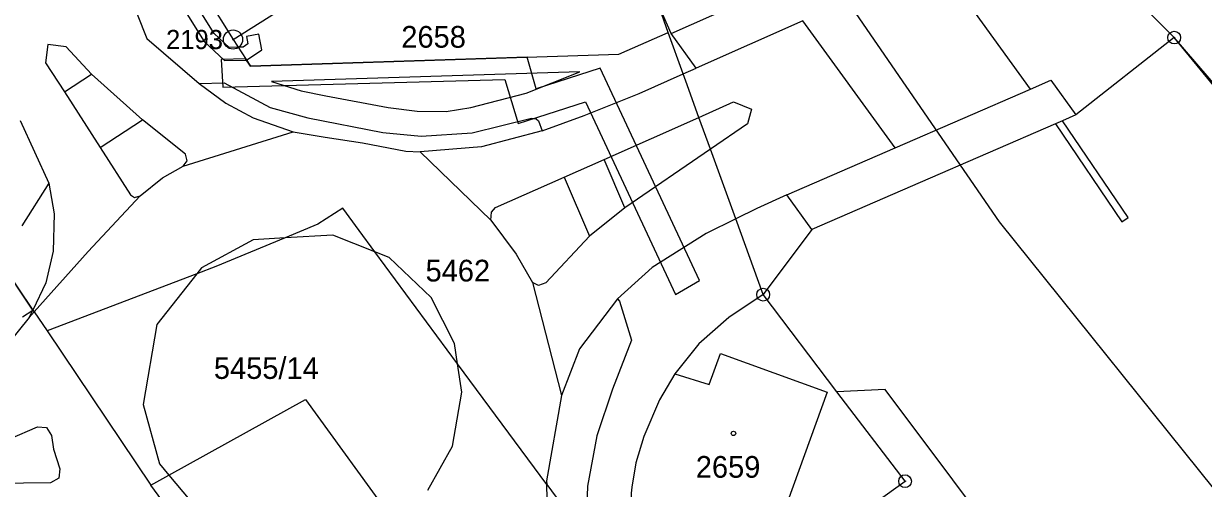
# Model space of a CAD drawing. Extents: x -821458 to -820266, y -1071458 to -1069826.
# Drawn here: x -820637.8 to -820545.4, y -1071330.5 to -1071294.1 of the extents above; entities that cross this region are included whole.
import ezdxf

# ---------------------------------------------------------------- set-up
doc = ezdxf.new("R2010")
doc.units = 0
for name, color, linetype in [('Vrstva 1', 7, 'Continuous'), ('Vrstva 13', 7, 'Continuous'), ('Vrstva 2', 7, 'Continuous'), ('Vrstva 4', 7, 'Continuous'), ('Vrstva 5', 7, 'Continuous'), ('Vrstva 6', 7, 'Continuous'), ('Vrstva 8', 7, 'Continuous')]:
    doc.layers.add(name, color=color, linetype=linetype)

msp = doc.modelspace()

# ---------------------------------------------------------------- linework, layer by layer
at = {"layer": 'Vrstva 1'}
for p, q in [((-820628.38, -1071284.03), (-820621.4, -1071295.3)), ((-820574.1, -1071322.9), (-820579.87, -1071315.28)), ((-820636.97, -1071316.64), (-820635.97, -1071318.12)), ((-820635.97, -1071318.12), (-820627.84, -1071330.19))]:
    msp.add_line(p, q, dxfattribs=at)
for points in [[(-820621.4, -1071295.3), (-820609.81, -1071287.99), (-820602.74, -1071283.57), (-820601.4, -1071282.71), (-820597.17, -1071279.98)], [(-820587.31, -1071294.74), (-820588.13, -1071292.45), (-820588.5, -1071292.71), (-820597.17, -1071279.98)], [(-820485.86, -1071372.383), (-820533.17, -1071312.78), (-820547.67, -1071295.15), (-820551.62, -1071291.15), (-820556.95, -1071290.24), (-820564.58, -1071281.57)], [(-820651.78, -1071294.5), (-820644.75, -1071305.17), (-820642.81, -1071308.03), (-820641.98, -1071309.26), (-820639.44, -1071313.01), (-820637.08, -1071316.49), (-820636.97, -1071316.64)], [(-820621.4, -1071295.3), (-820620.04, -1071297.4), (-820591.18, -1071296.46), (-820587.31, -1071294.74)], [(-820579.87, -1071315.28), (-820582.02, -1071309.35), (-820584, -1071303.9), (-820584.91, -1071301.4), (-820585.94, -1071298.56), (-820586.14, -1071298), (-820587.31, -1071294.74)], [(-820636.97, -1071316.64), (-820632.74, -1071311.9), (-820628.67, -1071307.54), (-820626.92, -1071306.13), (-820625.31, -1071305.23), (-820616.7, -1071302.53), (-820614.19, -1071302.96), (-820611.26, -1071303.39), (-820607.86, -1071304.05), (-820606.74, -1071304.09), (-820601.21, -1071309.45), (-820599.23, -1071312.11), (-820597.95, -1071314.34), (-820595.67, -1071323.19), (-820596.84, -1071329.86), (-820596.83, -1071330.15)], [(-820596.83, -1071330.15), (-820603.81, -1071320.7), (-820610.28, -1071311.94), (-820611.51, -1071310.27), (-820612.8, -1071308.52), (-820614.75, -1071309.77), (-820617.32, -1071310.83), (-820622.76, -1071313.08), (-820624.23, -1071313.64), (-820635.97, -1071318.12)], [(-820579.87, -1071315.28), (-820582.56, -1071317.06), (-820584.9, -1071319.14), (-820586.78, -1071321.49), (-820588, -1071323.53), (-820589.23, -1071326.4), (-820589.84, -1071328.44), (-820590.16, -1071330.36), (-820590.22, -1071330.83), (-820590.24, -1071333.93), (-820589.7, -1071337.1), (-820588.71, -1071340.28), (-820587.2, -1071343.19)], [(-820636.97, -1071316.64), (-820637.36, -1071317.08), (-820639.2, -1071319.35), (-820642.33, -1071322.43), (-820644.69, -1071324.22), (-820646.94, -1071325.71), (-820650.04, -1071327.31), (-820653.86, -1071329.02), (-820657.08, -1071330.4), (-820661.97, -1071331.85), (-820670.38, -1071333.7), (-820675.08, -1071335.1), (-820699.14, -1071345.77), (-820707.87, -1071352.56), (-820710.18, -1071353.88), (-820714.99, -1071355.97), (-820717.71, -1071357.17), (-820719.42, -1071357.95), (-820734.359, -1071365.197)], [(-820554.5, -1071343.84), (-820570.3, -1071322.7), (-820574.1, -1071322.9)], [(-820571.04, -1071331.54), (-820568.75, -1071329.89), (-820574.1, -1071322.9)], [(-820627.84, -1071330.19), (-820626.42, -1071329.41), (-820615.71, -1071323.48), (-820608.76, -1071333.11), (-820604.43, -1071339.12)], [(-820646.49, -1071330.09), (-820643.71, -1071328.69), (-820641.09, -1071327.51), (-820636.73, -1071325.64), (-820636, -1071325.69), (-820635.62, -1071326.31), (-820635.46, -1071327.37), (-820634.97, -1071328.91), (-820635.04, -1071329.66), (-820635.7, -1071330.02), (-820637.82, -1071330.05), (-820640.55, -1071330.14), (-820643.18, -1071330.76), (-820644.87, -1071331.37), (-820649.56, -1071333.47), (-820650.2, -1071333.24), (-820650.08, -1071332.51), (-820648.32, -1071331.22), (-820646.49, -1071330.09)], [(-820629.87, -1071337.4), (-820624.4, -1071334.89), (-820627.84, -1071330.19)], [(-820596.83, -1071330.15), (-820593.66, -1071334.44), (-820587.2, -1071343.19)], [(-820588.84, -1071349.46), (-820591.79, -1071345.45), (-820593.17, -1071343.03), (-820595.21, -1071338.98), (-820596.72, -1071334.72), (-820596.83, -1071330.15)]]:
    msp.add_lwpolyline(points, dxfattribs=at)
at = {"layer": 'Vrstva 13'}
for points in [[(-820650.46, -1071253.28), (-820636.39, -1071275.54), (-820629.91, -1071285.45), (-820623.66, -1071295.46), (-820622.08, -1071296.95), (-820620.34, -1071296.92), (-820619.15, -1071296.11), (-820619.37, -1071294.88), (-820620.35, -1071295.06), (-820620.25, -1071295.65), (-820620.61, -1071295.9), (-820621, -1071295.91), (-820621.7, -1071295.93), (-820622.88, -1071294.82), (-820628.8, -1071285.34), (-820627.91, -1071284.78), (-820628.38, -1071284.03), (-820628.44, -1071283.93), (-820629.34, -1071284.49), (-820635.43, -1071275.04), (-820634.47, -1071274.43), (-820635, -1071273.59), (-820635.97, -1071274.2), (-820643.14, -1071263.21)], [(-820637.9, -1071317.01), (-820637.08, -1071316.49), (-820638.4, -1071314.54)]]:
    msp.add_lwpolyline(points, dxfattribs=at)
msp.add_lwpolyline([(-820622.33, -1071296.86), (-820622.21, -1071299.02), (-820600.11, -1071298.43), (-820599.06, -1071301.87), (-820593.79, -1071300.18), (-820586.74, -1071315.27), (-820584.86, -1071314.18), (-820592.63, -1071297.54), (-820597.64, -1071299.15), (-820598.35, -1071296.69), (-820620.04, -1071297.4), (-820620.42, -1071296.81)], close=True, dxfattribs=at)
at = {"layer": 'Vrstva 4'}
for p, q in [((-820558.94, -1071299.19), (-820566.17, -1071289.15)), ((-820587.08, -1071294.82), (-820578.74, -1071291.13)), ((-820587.08, -1071294.82), (-820588.13, -1071292.45)), ((-820628.9, -1071293.32), (-820628.16, -1071295.22)), ((-820576.77, -1071293.84), (-820585.13, -1071297.55)), ((-820569.54, -1071303.79), (-820576.77, -1071293.84)), ((-820628.16, -1071295.22), (-820624.05, -1071298.74)), ((-820585.13, -1071297.55), (-820587.08, -1071294.82)), ((-820547.67, -1071295.15), (-820555.37, -1071301.21)), ((-820486.8, -1071365.91), (-820547.67, -1071295.15)), ((-820635.9, -1071295.68), (-820636.09, -1071297.12)), ((-820634.47, -1071295.88), (-820635.9, -1071295.68)), ((-820632.48, -1071298.01), (-820634.47, -1071295.88)), ((-820636.09, -1071297.12), (-820634.61, -1071299.39)), ((-820634.61, -1071299.39), (-820632.48, -1071298.01)), ((-820628.5, -1071301.58), (-820632.48, -1071298.01)), ((-820594.22, -1071297.82), (-820618.38, -1071298.58)), ((-820598.44, -1071299.5), (-820594.22, -1071297.82)), ((-820589.59, -1071299.52), (-820586.14, -1071298)), ((-820586.14, -1071298), (-820585.13, -1071297.55)), ((-820624.05, -1071298.74), (-820622.1, -1071298.7)), ((-820624.05, -1071298.74), (-820621.97, -1071300.28)), ((-820622.1, -1071298.7), (-820618.49, -1071300.63)), ((-820618.38, -1071298.58), (-820616.07, -1071299.32)), ((-820558.94, -1071299.19), (-820557.34, -1071298.49)), ((-820557.34, -1071298.49), (-820555.37, -1071301.21)), ((-820634.61, -1071299.39), (-820631.81, -1071303.75)), ((-820616.07, -1071299.32), (-820614.12, -1071299.71)), ((-820614.12, -1071299.71), (-820609.25, -1071300.63)), ((-820602.77, -1071300.62), (-820598.44, -1071299.5)), ((-820593.89, -1071301.26), (-820589.59, -1071299.52)), ((-820569.54, -1071303.79), (-820558.94, -1071299.19)), ((-820621.97, -1071300.28), (-820619.83, -1071301.44)), ((-820618.49, -1071300.63), (-820615.55, -1071301.43)), ((-820609.25, -1071300.63), (-820606.98, -1071300.9)), ((-820604.71, -1071300.94), (-820602.77, -1071300.62)), ((-820584.91, -1071301.4), (-820582.19, -1071300.19)), ((-820582.19, -1071300.19), (-820580.79, -1071300.76)), ((-820580.79, -1071300.76), (-820581.09, -1071301.91)), ((-820638.08, -1071301.63), (-820635.84, -1071306.55)), ((-820631.81, -1071303.75), (-820628.5, -1071301.58)), ((-820625.13, -1071304.27), (-820628.5, -1071301.58)), ((-820619.83, -1071301.44), (-820616.7, -1071302.53)), ((-820615.55, -1071301.43), (-820609.66, -1071302.59)), ((-820606.98, -1071300.9), (-820604.71, -1071300.94)), ((-820602.67, -1071302.62), (-820598.01, -1071301.46)), ((-820598.01, -1071301.46), (-820597.66, -1071301.51)), ((-820597.66, -1071301.51), (-820597.46, -1071301.67)), ((-820597.46, -1071301.67), (-820597.18, -1071302.44)), ((-820597.18, -1071302.44), (-820593.89, -1071301.26)), ((-820592.33, -1071304.69), (-820584.91, -1071301.4)), ((-820556.42, -1071301.67), (-820556.98, -1071301.91)), ((-820555.37, -1071301.21), (-820556.42, -1071301.67)), ((-820551.27, -1071309.23), (-820556.42, -1071301.67)), ((-820609.66, -1071302.59), (-820606.66, -1071302.86)), ((-820606.66, -1071302.86), (-820602.67, -1071302.62)), ((-820597.18, -1071302.44), (-820601.93, -1071303.7)), ((-820581.09, -1071301.91), (-820584, -1071303.9)), ((-820556.98, -1071301.91), (-820567.57, -1071306.5)), ((-820556.98, -1071301.91), (-820551.77, -1071309.57)), ((-820631.81, -1071303.75), (-820629.42, -1071307.46)), ((-820624.98, -1071304.8), (-820625.13, -1071304.27)), ((-820601.93, -1071303.7), (-820606.74, -1071304.09)), ((-820584, -1071303.9), (-820590.7, -1071308.49)), ((-820578.01, -1071307.47), (-820569.54, -1071303.79)), ((-820625.31, -1071305.23), (-820624.98, -1071304.8)), ((-820595.46, -1071306.08), (-820592.33, -1071304.69)), ((-820590.7, -1071308.49), (-820592.33, -1071304.69)), ((-820600.83, -1071308.45), (-820595.46, -1071306.08)), ((-820595.46, -1071306.08), (-820593.47, -1071310.69)), ((-820635.84, -1071306.55), (-820637.95, -1071309.88)), ((-820635.84, -1071306.55), (-820635.41, -1071308.94)), ((-820567.57, -1071306.5), (-820576.06, -1071310.19)), ((-820629.42, -1071307.46), (-820629.11, -1071307.66)), ((-820629.11, -1071307.66), (-820628.67, -1071307.54)), ((-820578.01, -1071307.47), (-820580.37, -1071308.53)), ((-820576.06, -1071310.19), (-820578.01, -1071307.47)), ((-820635.41, -1071308.94), (-820635.48, -1071311.87)), ((-820601.21, -1071309.45), (-820601.16, -1071308.83)), ((-820601.16, -1071308.83), (-820600.83, -1071308.45)), ((-820590.7, -1071308.49), (-820593.47, -1071310.69)), ((-820580.37, -1071308.53), (-820582.02, -1071309.35)), ((-820582.02, -1071309.35), (-820584.34, -1071310.49)), ((-820551.77, -1071309.57), (-820551.27, -1071309.23)), ((-820619.82, -1071310.98), (-820623.87, -1071313.18)), ((-820617.32, -1071310.83), (-820619.82, -1071310.98)), ((-820613.58, -1071310.61), (-820617.32, -1071310.83)), ((-820610.28, -1071311.94), (-820613.58, -1071310.61)), ((-820593.47, -1071310.69), (-820596.9, -1071314.36)), ((-820584.34, -1071310.49), (-820588.56, -1071313.16)), ((-820576.06, -1071310.19), (-820579.87, -1071315.28)), ((-820635.48, -1071311.87), (-820636.07, -1071314.36)), ((-820609.18, -1071312.38), (-820610.28, -1071311.94)), ((-820605.88, -1071315.5), (-820609.18, -1071312.38)), ((-820624.23, -1071313.64), (-820627.36, -1071317.62)), ((-820623.87, -1071313.18), (-820624.23, -1071313.64)), ((-820588.56, -1071313.16), (-820591.29, -1071315.61)), ((-820636.07, -1071314.36), (-820637.08, -1071316.49)), ((-820597.47, -1071314.56), (-820597.95, -1071314.34)), ((-820596.9, -1071314.36), (-820597.47, -1071314.56)), ((-820604.05, -1071319.1), (-820605.88, -1071315.5)), ((-820591.29, -1071315.61), (-820594.25, -1071319.53)), ((-820591.29, -1071315.61), (-820591.12, -1071315.79)), ((-820637.36, -1071317.08), (-820637.08, -1071316.49)), ((-820591.12, -1071315.79), (-820590.19, -1071318.84)), ((-820627.36, -1071317.62), (-820628.45, -1071323.89)), ((-820603.81, -1071320.7), (-820604.05, -1071319.1)), ((-820590.19, -1071318.84), (-820591.66, -1071322.69)), ((-820594.25, -1071319.53), (-820595.67, -1071323.19)), ((-820584.11, -1071322.31), (-820583.2, -1071319.9)), ((-820583.2, -1071319.9), (-820574.86, -1071322.92)), ((-820603.47, -1071322.93), (-820603.81, -1071320.7)), ((-820586.78, -1071321.49), (-820584.11, -1071322.31)), ((-820604.21, -1071327.14), (-820603.47, -1071322.93)), ((-820591.66, -1071322.69), (-820592.89, -1071326.34)), ((-820574.86, -1071322.92), (-820577.97, -1071331.52)), ((-820628.45, -1071323.89), (-820627.15, -1071328.54)), ((-820592.89, -1071326.34), (-820593.63, -1071330.28)), ((-820606.13, -1071330.6), (-820604.21, -1071327.14)), ((-820627.15, -1071328.54), (-820626.42, -1071329.41)), ((-820626.42, -1071329.41), (-820623.54, -1071332.85)), ((-820593.63, -1071330.28), (-820593.74, -1071333.61))]:
    msp.add_line(p, q, dxfattribs=at)
at = {"layer": 'Vrstva 5'}
msp.add_circle((-820582.197, -1071326.149), 0.175, dxfattribs=at)
at = {"layer": 'Vrstva 6'}
for p, q in [((-820561.35, -1071309.57), (-820596.75, -1071258.19)), ((-820526.35, -1071353.17), (-820561.35, -1071309.57))]:
    msp.add_line(p, q, dxfattribs=at)
at = {"layer": 'Vrstva 8'}
for centre, radius in [((-820621.4, -1071295.3), 0.75), ((-820621.4, -1071295.3), 0.03), ((-820547.67, -1071295.15), 0.5), ((-820547.67, -1071295.15), 0.0303), ((-820579.87, -1071315.28), 0.5), ((-820579.87, -1071315.28), 0.0303), ((-820568.75, -1071329.89), 0.5), ((-820568.75, -1071329.89), 0.0303)]:
    msp.add_circle(centre, radius, dxfattribs=at)

# ---------------------------------------------------------------- texts
at = {"layer": 'Vrstva 2'}
for s, p in [('2658', (-820608.217, -1071295.94)), ('5462', (-820606.317, -1071314.249)), ('5455/14', (-820622.898, -1071321.88)), ('2659', (-820585.147, -1071329.62))]:
    msp.add_text(s, height=1.7, dxfattribs=at).set_placement(p)
at = {"layer": 'Vrstva 8'}
msp.add_text('2193', height=1.5, dxfattribs=at).set_placement((-820626.648, -1071296.05))

doc.saveas('drawing.dxf')
